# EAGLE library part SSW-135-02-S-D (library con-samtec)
THROUGH-HOLE .025" SQ POST SOCKET Source: Samtec SSW.pdf
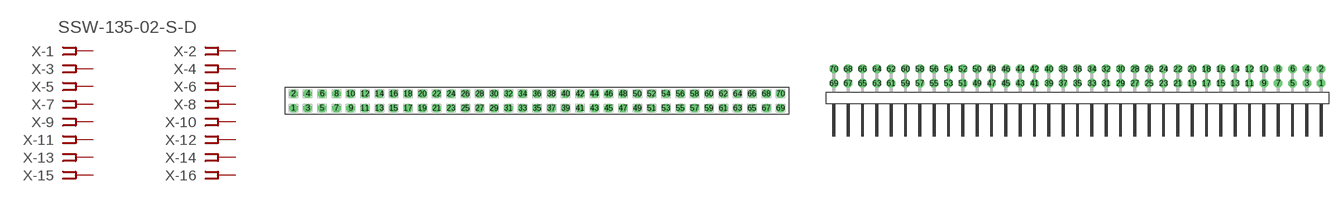
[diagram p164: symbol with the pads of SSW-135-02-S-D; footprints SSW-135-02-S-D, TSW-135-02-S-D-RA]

Designator prefix X; gates -1=FPINV -2=FPIN -3=FPIN -4=FPIN -5=FPIN -6=FPIN -7=FPIN -8=FPIN -9=FPIN -10=FPIN -11=FPIN -12=FPIN -13=FPIN -14=FPIN -15=FPIN -16=FPIN -17=FPIN -18=FPIN -19=FPIN -20=FPIN -21=FPIN -22=FPIN -23=FPIN -24=FPIN -25=FPIN -26=FPIN -27=FPIN -28=FPIN -29=FPIN -30=FPIN -31=FPIN -32=FPIN -33=FPIN -34=FPIN -35=FPIN -36=FPIN -37=FPIN -38=FPIN -39=FPIN -40=FPIN -41=FPIN -42=FPIN -43=FPIN -44=FPIN -45=FPIN -46=FPIN -47=FPIN -48=FPIN -49=FPIN -50=FPIN -51=FPIN -52=FPIN -53=FPIN -54=FPIN -55=FPIN -56=FPIN -57=FPIN -58=FPIN -59=FPIN -60=FPIN -61=FPIN -62=FPIN -63=FPIN -64=FPIN -65=FPIN -66=FPIN -67=FPIN -68=FPIN -69=FPIN -70=FPIN

## SSW-135-02-S-D (MPN: SSW-135-02-S-D; OC_FARNELL: unknown; OC_NEWARK: 11P9886)  [SSW-135-02-S-D]
1  -1:1  pas
2  -2:1  pas
3  -3:1  pas
4  -4:1  pas
5  -5:1  pas
6  -6:1  pas
7  -7:1  pas
8  -8:1  pas
9  -9:1  pas
10  -10:1  pas
11  -11:1  pas
12  -12:1  pas
13  -13:1  pas
14  -14:1  pas
15  -15:1  pas
16  -16:1  pas
17  -17:1  pas
18  -18:1  pas
19  -19:1  pas
20  -20:1  pas
21  -21:1  pas
22  -22:1  pas
23  -23:1  pas
24  -24:1  pas
25  -25:1  pas
26  -26:1  pas
27  -27:1  pas
28  -28:1  pas
29  -29:1  pas
30  -30:1  pas
31  -31:1  pas
32  -32:1  pas
33  -33:1  pas
34  -34:1  pas
35  -35:1  pas
36  -36:1  pas
37  -37:1  pas
38  -38:1  pas
39  -39:1  pas
40  -40:1  pas
41  -41:1  pas
42  -42:1  pas
43  -43:1  pas
44  -44:1  pas
45  -45:1  pas
46  -46:1  pas
47  -47:1  pas
48  -48:1  pas
49  -49:1  pas
50  -50:1  pas
51  -51:1  pas
52  -52:1  pas
53  -53:1  pas
54  -54:1  pas
55  -55:1  pas
56  -56:1  pas
57  -57:1  pas
58  -58:1  pas
59  -59:1  pas
60  -60:1  pas
61  -61:1  pas
62  -62:1  pas
63  -63:1  pas
64  -64:1  pas
65  -65:1  pas
66  -66:1  pas
67  -67:1  pas
68  -68:1  pas
69  -69:1  pas
70  -70:1  pas

## SSW-135-02-S-D-RA (MPN: SSW-135-02-S-D-RA; OC_FARNELL: unknown; OC_NEWARK: 11P9887)  [TSW-135-02-S-D-RA]
Pads as for SSW-135-02-S-D

## Footprint SSW-135-02-S-D (pad centres in mm)
THROUGH-HOLE .025" SQ POST SOCKET Source: Samtec SSW.pdf
drill 1 pad 1.5 octagon: 1 -43.18,-1.27; 2 -43.18,1.27; 3 -40.64,-1.27; 4 -40.64,1.27; 5 -38.1,-1.27; 6 -38.1,1.27; 7 -35.56,-1.27; 8 -35.56,1.27; 9 -33.02,-1.27; 10 -33.02,1.27; 11 -30.48,-1.27; 12 -30.48,1.27; 13 -27.94,-1.27; 14 -27.94,1.27; 15 -25.4,-1.27; 16 -25.4,1.27; 17 -22.86,-1.27; 18 -22.86,1.27; 19 -20.32,-1.27; 20 -20.32,1.27; 21 -17.78,-1.27; 22 -17.78,1.27; 23 -15.24,-1.27; 24 -15.24,1.27; 25 -12.7,-1.27; 26 -12.7,1.27; 27 -10.16,-1.27; 28 -10.16,1.27; 29 -7.62,-1.27; 30 -7.62,1.27; 31 -5.08,-1.27; 32 -5.08,1.27; 33 -2.54,-1.27; 34 -2.54,1.27; 35 0,-1.27; 36 0,1.27; 37 2.54,-1.27; 38 2.54,1.27; 39 5.08,-1.27; 40 5.08,1.27; 41 7.62,-1.27; 42 7.62,1.27; 43 10.16,-1.27; 44 10.16,1.27; 45 12.7,-1.27; 46 12.7,1.27; 47 15.24,-1.27; 48 15.24,1.27; 49 17.78,-1.27; 50 17.78,1.27; 51 20.32,-1.27; 52 20.32,1.27; 53 22.86,-1.27; 54 22.86,1.27; 55 25.4,-1.27; 56 25.4,1.27; 57 27.94,-1.27; 58 27.94,1.27; 59 30.48,-1.27; 60 30.48,1.27; 61 33.02,-1.27; 62 33.02,1.27; 63 35.56,-1.27; 64 35.56,1.27; 65 38.1,-1.27; 66 38.1,1.27; 67 40.64,-1.27; 68 40.64,1.27; 69 43.18,-1.27; 70 43.18,1.27

## Footprint TSW-135-02-S-D-RA (pad centres in mm)
THROUGH-HOLE .025" SQ POST HEADER Source: Samtec TSW.pdf
drill 1 pad 1.5 octagon: 1 43.18,1.524; 2 43.18,4.064; 3 40.64,1.524; 4 40.64,4.064; 5 38.1,1.524; 6 38.1,4.064; 7 35.56,1.524; 8 35.56,4.064; 9 33.02,1.524; 10 33.02,4.064; 11 30.48,1.524; 12 30.48,4.064; 13 27.94,1.524; 14 27.94,4.064; 15 25.4,1.524; 16 25.4,4.064; 17 22.86,1.524; 18 22.86,4.064; 19 20.32,1.524; 20 20.32,4.064; 21 17.78,1.524; 22 17.78,4.064; 23 15.24,1.524; 24 15.24,4.064; 25 12.7,1.524; 26 12.7,4.064; 27 10.16,1.524; 28 10.16,4.064; 29 7.62,1.524; 30 7.62,4.064; 31 5.08,1.524; 32 5.08,4.064; 33 2.54,1.524; 34 2.54,4.064; 35 0,1.524; 36 0,4.064; 37 -2.54,1.524; 38 -2.54,4.064; 39 -5.08,1.524; 40 -5.08,4.064; 41 -7.62,1.524; 42 -7.62,4.064; 43 -10.16,1.524; 44 -10.16,4.064; 45 -12.7,1.524; 46 -12.7,4.064; 47 -15.24,1.524; 48 -15.24,4.064; 49 -17.78,1.524; 50 -17.78,4.064; 51 -20.32,1.524; 52 -20.32,4.064; 53 -22.86,1.524; 54 -22.86,4.064; 55 -25.4,1.524; 56 -25.4,4.064; 57 -27.94,1.524; 58 -27.94,4.064; 59 -30.48,1.524; 60 -30.48,4.064; 61 -33.02,1.524; 62 -33.02,4.064; 63 -35.56,1.524; 64 -35.56,4.064; 65 -38.1,1.524; 66 -38.1,4.064; 67 -40.64,1.524; 68 -40.64,4.064; 69 -43.18,1.524; 70 -43.18,4.064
